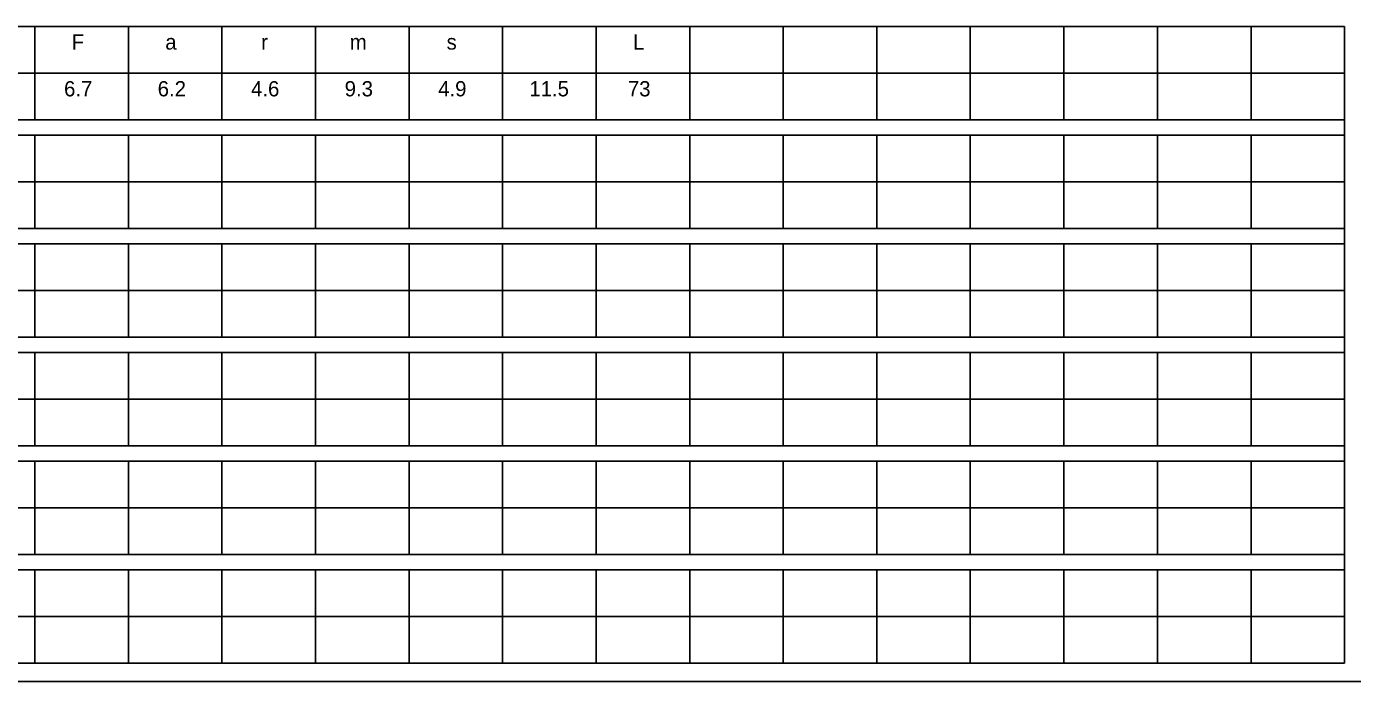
# Model space of a CAD drawing. Extents: x -998.8 to -961.2, y -2311.8 to -2287.8.
# Drawn here: x -990.75 to -980.09, y -2299.56 to -2294.29 of the extents above; entities that cross this region are included whole.
import ezdxf

# ---------------------------------------------------------------- set-up
doc = ezdxf.new("R2010")
doc.units = 0
doc.layers.add('GSSign', color=7, linetype='Continuous')
doc.layers.add('SheetLinesMisc2_dp', color=7, linetype='Continuous')

msp = doc.modelspace()

# ---------------------------------------------------------------- linework, layer by layer
at = {"layer": 'SheetLinesMisc2_dp'}
for p, q in [((-998.646, -2294.286), (-980.149, -2294.286)), ((-990.683, -2294.286), (-990.683, -2295.038)), ((-989.931, -2294.286), (-989.931, -2295.038)), ((-989.178, -2294.286), (-989.178, -2295.038)), ((-988.426, -2294.286), (-988.426, -2295.038)), ((-987.673, -2294.286), (-987.673, -2295.038)), ((-986.921, -2294.286), (-986.921, -2295.038)), ((-986.168, -2294.286), (-986.168, -2295.038)), ((-985.416, -2294.286), (-985.416, -2295.038)), ((-984.664, -2294.286), (-984.664, -2295.038)), ((-983.911, -2294.286), (-983.911, -2295.038)), ((-983.159, -2294.286), (-983.159, -2295.038)), ((-982.406, -2294.286), (-982.406, -2295.038)), ((-981.654, -2294.286), (-981.654, -2295.038)), ((-980.901, -2294.286), (-980.901, -2295.038)), ((-980.149, -2299.407), (-980.149, -2294.286)), ((-998.646, -2294.662), (-980.149, -2294.662)), ((-998.646, -2295.038), (-980.149, -2295.038)), ((-998.646, -2295.16), (-980.149, -2295.16)), ((-990.683, -2295.16), (-990.683, -2295.912)), ((-989.931, -2295.16), (-989.931, -2295.912)), ((-989.178, -2295.16), (-989.178, -2295.912)), ((-988.426, -2295.16), (-988.426, -2295.912)), ((-987.673, -2295.16), (-987.673, -2295.912)), ((-986.921, -2295.16), (-986.921, -2295.912)), ((-986.168, -2295.16), (-986.168, -2295.912)), ((-985.416, -2295.16), (-985.416, -2295.912)), ((-984.664, -2295.16), (-984.664, -2295.912)), ((-983.911, -2295.16), (-983.911, -2295.912)), ((-983.159, -2295.16), (-983.159, -2295.912)), ((-982.406, -2295.16), (-982.406, -2295.912)), ((-981.654, -2295.16), (-981.654, -2295.912)), ((-980.901, -2295.16), (-980.901, -2295.912)), ((-998.646, -2295.536), (-980.149, -2295.536)), ((-998.646, -2295.912), (-980.149, -2295.912)), ((-998.646, -2296.034), (-980.149, -2296.034)), ((-990.683, -2296.034), (-990.683, -2296.785)), ((-989.931, -2296.034), (-989.931, -2296.785)), ((-989.178, -2296.034), (-989.178, -2296.785)), ((-988.426, -2296.034), (-988.426, -2296.785)), ((-987.673, -2296.034), (-987.673, -2296.785)), ((-986.921, -2296.034), (-986.921, -2296.785)), ((-986.168, -2296.034), (-986.168, -2296.785)), ((-985.416, -2296.034), (-985.416, -2296.785)), ((-984.664, -2296.034), (-984.664, -2296.785)), ((-983.911, -2296.034), (-983.911, -2296.785)), ((-983.159, -2296.034), (-983.159, -2296.785)), ((-982.406, -2296.034), (-982.406, -2296.785)), ((-981.654, -2296.034), (-981.654, -2296.785)), ((-980.901, -2296.034), (-980.901, -2296.785)), ((-998.646, -2296.41), (-980.149, -2296.41)), ((-998.646, -2296.785), (-980.149, -2296.785)), ((-998.646, -2296.908), (-980.149, -2296.908)), ((-990.683, -2296.908), (-990.683, -2297.66)), ((-989.931, -2296.908), (-989.931, -2297.66)), ((-989.178, -2296.908), (-989.178, -2297.66)), ((-988.426, -2296.908), (-988.426, -2297.66)), ((-987.673, -2296.908), (-987.673, -2297.66)), ((-986.921, -2296.908), (-986.921, -2297.66)), ((-986.168, -2296.908), (-986.168, -2297.66)), ((-985.416, -2296.908), (-985.416, -2297.66)), ((-984.664, -2296.908), (-984.664, -2297.66)), ((-983.911, -2296.908), (-983.911, -2297.66)), ((-983.159, -2296.908), (-983.159, -2297.66)), ((-982.406, -2296.908), (-982.406, -2297.66)), ((-981.654, -2296.908), (-981.654, -2297.66)), ((-980.901, -2296.908), (-980.901, -2297.66)), ((-998.646, -2297.284), (-980.149, -2297.284)), ((-998.646, -2297.66), (-980.149, -2297.66)), ((-998.646, -2297.782), (-980.149, -2297.782)), ((-990.683, -2297.782), (-990.683, -2298.534)), ((-989.931, -2297.782), (-989.931, -2298.534)), ((-989.178, -2297.782), (-989.178, -2298.534)), ((-988.426, -2297.782), (-988.426, -2298.534)), ((-987.673, -2297.782), (-987.673, -2298.534)), ((-986.921, -2297.782), (-986.921, -2298.534)), ((-986.168, -2297.782), (-986.168, -2298.534)), ((-985.416, -2297.782), (-985.416, -2298.534)), ((-984.664, -2297.782), (-984.664, -2298.534)), ((-983.911, -2297.782), (-983.911, -2298.534)), ((-983.159, -2297.782), (-983.159, -2298.534)), ((-982.406, -2297.782), (-982.406, -2298.534)), ((-981.654, -2297.782), (-981.654, -2298.534)), ((-980.901, -2297.782), (-980.901, -2298.534)), ((-998.646, -2298.158), (-980.149, -2298.158)), ((-998.646, -2298.534), (-980.149, -2298.534)), ((-998.646, -2298.656), (-980.149, -2298.656)), ((-990.683, -2298.656), (-990.683, -2299.407)), ((-989.931, -2298.656), (-989.931, -2299.407)), ((-989.178, -2298.656), (-989.178, -2299.407)), ((-988.426, -2298.656), (-988.426, -2299.407)), ((-987.673, -2298.656), (-987.673, -2299.407)), ((-986.921, -2298.656), (-986.921, -2299.407)), ((-986.168, -2298.656), (-986.168, -2299.407)), ((-985.416, -2298.656), (-985.416, -2299.407)), ((-984.664, -2298.656), (-984.664, -2299.407)), ((-983.911, -2298.656), (-983.911, -2299.407)), ((-983.159, -2298.656), (-983.159, -2299.407)), ((-982.406, -2298.656), (-982.406, -2299.407)), ((-981.654, -2298.656), (-981.654, -2299.407)), ((-980.901, -2298.656), (-980.901, -2299.407)), ((-998.646, -2299.032), (-980.149, -2299.032)), ((-998.646, -2299.407), (-980.149, -2299.407)), ((-998.826, -2299.555), (-961.216, -2299.555))]:
    msp.add_line(p, q, dxfattribs=at)

# ---------------------------------------------------------------- texts
at = {"layer": 'GSSign'}
for s, height, p in [('F', 0.122, (-990.387, -2294.472)), ('a', 0.122, (-989.634, -2294.472)), ('r', 0.122, (-988.863, -2294.472)), ('m', 0.122, (-988.15, -2294.472)), ('s', 0.122, (-987.371, -2294.472)), ('L', 0.122, (-985.872, -2294.472)), ('6.7', 0.1225, (-990.448, -2294.848)), ('6.2', 0.1225, (-989.695, -2294.848)), ('4.6', 0.1225, (-988.944, -2294.848)), ('9.3', 0.1225, (-988.191, -2294.848)), ('4.9', 0.1225, (-987.439, -2294.848)), ('11.5', 0.1225, (-986.706, -2294.848)), ('73', 0.1225, (-985.913, -2294.848))]:
    msp.add_text(s, height=height, dxfattribs=at).set_placement(p)

doc.saveas('drawing.dxf')
